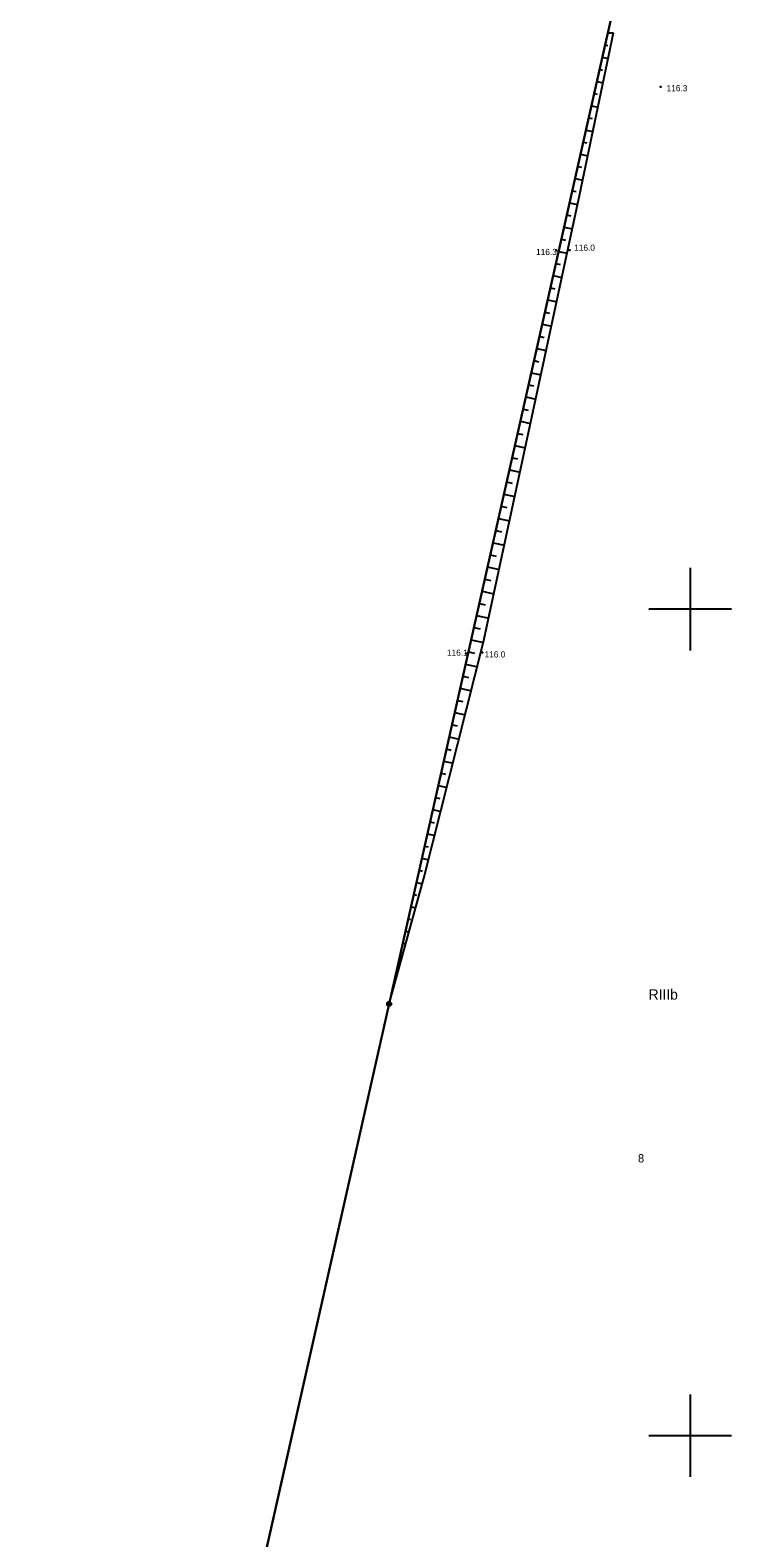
# Model space of a CAD drawing. Extents: x 6424617 to 6425697, y 5665845 to 5667190.
# Drawn here: x 6424820.1 to 6424906, y 5666387.6 to 5666570.1 of the extents above; entities that cross this region are included whole.
import ezdxf

# ---------------------------------------------------------------- set-up
doc = ezdxf.new("R2010")
doc.units = 0
for name, color, linetype in [('Warstwa 1', 7, 'Continuous'), ('Warstwa 10', 7, 'Continuous'), ('Warstwa 13', 7, 'Continuous'), ('Warstwa 15', 7, 'Continuous'), ('Warstwa 2', 7, 'Continuous'), ('Warstwa 20', 7, 'Continuous'), ('Warstwa 21', 7, 'Continuous'), ('Warstwa 6', 7, 'Continuous'), ('Warstwa 63', 7, 'Continuous')]:
    doc.layers.add(name, color=color, linetype=linetype)

msp = doc.modelspace()

# ---------------------------------------------------------------- linework, layer by layer
at = {"layer": 'Warstwa 1'}
for p, q in [((6424863.57, 5666452.24), (6424895.16, 5666592.47)), ((6424863.57, 5666452.24), (6424895.16, 5666592.47)), ((6424835.21, 5666326.25), (6424863.57, 5666452.24)), ((6424835.21, 5666326.25), (6424863.57, 5666452.24))]:
    msp.add_line(p, q, dxfattribs=at)
at = {"layer": 'Warstwa 10'}
for p, q in [((6424863.57, 5666452.24), (6424890.03, 5666569.72)), ((6424886.61, 5666550.03), (6424890.71, 5666569.71)), ((6424890.03, 5666569.72), (6424890.71, 5666569.71)), ((6424890.03, 5666569.72), (6424890.71, 5666569.71)), ((6424889.7, 5666568.25), (6424890.04, 5666568.21)), ((6424889.37, 5666566.78), (6424890.06, 5666566.63)), ((6424889.04, 5666565.32), (6424889.4, 5666565.23)), ((6424888.38, 5666562.38), (6424888.76, 5666562.29)), ((6424888.71, 5666563.85), (6424889.45, 5666563.68)), ((6424888.05, 5666560.91), (6424888.84, 5666560.73)), ((6424887.72, 5666559.44), (6424888.12, 5666559.35)), ((6424887.39, 5666557.97), (6424888.22, 5666557.78)), ((6424886.73, 5666555.04), (6424887.61, 5666554.83)), ((6424887.06, 5666556.5), (6424887.49, 5666556.41)), ((6424886.39, 5666553.57), (6424886.85, 5666553.46)), ((6424886.06, 5666552.1), (6424887, 5666551.89)), ((6424875, 5666496.03), (6424886.61, 5666550.03)), ((6424885.73, 5666550.63), (6424886.21, 5666550.52)), ((6424885.07, 5666547.69), (6424885.57, 5666547.58)), ((6424885.4, 5666549.16), (6424886.38, 5666548.94)), ((6424884.74, 5666546.23), (6424885.75, 5666546)), ((6424884.41, 5666544.76), (6424884.92, 5666544.64)), ((6424884.08, 5666543.29), (6424885.11, 5666543.05)), ((6424883.42, 5666540.35), (6424884.48, 5666540.11)), ((6424883.75, 5666541.82), (6424884.27, 5666541.7)), ((6424883.09, 5666538.88), (6424883.62, 5666538.76)), ((6424882.76, 5666537.41), (6424883.85, 5666537.17)), ((6424882.42, 5666535.95), (6424882.98, 5666535.82)), ((6424881.76, 5666533.01), (6424882.33, 5666532.88)), ((6424882.09, 5666534.48), (6424883.21, 5666534.22)), ((6424881.43, 5666531.54), (6424882.58, 5666531.28)), ((6424881.1, 5666530.07), (6424881.68, 5666529.94)), ((6424880.77, 5666528.6), (6424881.95, 5666528.34)), ((6424880.11, 5666525.67), (6424881.32, 5666525.39)), ((6424880.44, 5666527.13), (6424881.04, 5666527)), ((6424879.78, 5666524.2), (6424880.39, 5666524.06)), ((6424879.45, 5666522.73), (6424880.68, 5666522.45)), ((6424879.12, 5666521.26), (6424879.74, 5666521.12)), ((6424878.46, 5666518.32), (6424879.1, 5666518.18)), ((6424878.79, 5666519.79), (6424880.05, 5666519.5)), ((6424878.13, 5666516.85), (6424879.42, 5666516.57)), ((6424877.79, 5666515.39), (6424878.45, 5666515.24)), ((6424877.46, 5666513.92), (6424878.79, 5666513.62)), ((6424877.13, 5666512.45), (6424877.8, 5666512.3)), ((6424876.47, 5666509.51), (6424877.15, 5666509.36)), ((6424876.8, 5666510.98), (6424878.15, 5666510.67)), ((6424876.14, 5666508.04), (6424877.52, 5666507.73)), ((6424875.81, 5666506.58), (6424876.51, 5666506.42)), ((6424875.48, 5666505.11), (6424876.89, 5666504.78)), ((6424874.82, 5666502.17), (6424876.25, 5666501.84)), ((6424875.15, 5666503.64), (6424875.86, 5666503.48)), ((6424874.49, 5666500.7), (6424875.21, 5666500.54)), ((6424874.16, 5666499.23), (6424875.62, 5666498.9)), ((6424873.83, 5666497.76), (6424874.57, 5666497.6)), ((6424867.79, 5666467.44), (6424875, 5666496.03)), ((6424873.16, 5666494.83), (6424873.89, 5666494.66)), ((6424873.5, 5666496.3), (6424874.99, 5666495.96)), ((6424872.83, 5666493.36), (6424874.25, 5666493.04)), ((6424872.5, 5666491.89), (6424873.19, 5666491.74)), ((6424872.17, 5666490.42), (6424873.51, 5666490.12)), ((6424871.51, 5666487.49), (6424872.78, 5666487.2)), ((6424871.84, 5666488.95), (6424872.49, 5666488.81)), ((6424871.18, 5666486.02), (6424871.79, 5666485.88)), ((6424870.85, 5666484.55), (6424872.04, 5666484.28)), ((6424870.52, 5666483.08), (6424871.09, 5666482.95)), ((6424869.86, 5666480.14), (6424870.39, 5666480.02)), ((6424870.19, 5666481.61), (6424871.3, 5666481.36)), ((6424869.53, 5666478.67), (6424870.56, 5666478.44)), ((6424869.2, 5666477.21), (6424869.7, 5666477.09)), ((6424868.86, 5666475.74), (6424869.83, 5666475.52)), ((6424868.2, 5666472.8), (6424869.09, 5666472.6)), ((6424868.53, 5666474.27), (6424869, 5666474.16)), ((6424867.87, 5666471.33), (6424868.3, 5666471.24)), ((6424867.54, 5666469.86), (6424868.35, 5666469.68)), ((6424863.57, 5666452.24), (6424867.79, 5666467.44)), ((6424867.21, 5666468.4), (6424867.59, 5666468.31)), ((6424866.55, 5666465.46), (6424866.87, 5666465.38)), ((6424866.88, 5666466.93), (6424867.6, 5666466.76)), ((6424866.22, 5666463.99), (6424866.79, 5666463.86)), ((6424865.89, 5666462.52), (6424866.14, 5666462.46)), ((6424865.56, 5666461.05), (6424865.99, 5666460.96)), ((6424864.9, 5666458.12), (6424865.18, 5666458.05)), ((6424865.23, 5666459.58), (6424865.41, 5666459.54)), ((6424864.57, 5666456.65), (6424864.67, 5666456.62)), ((6424864.23, 5666455.18), (6424864.38, 5666455.15))]:
    msp.add_line(p, q, dxfattribs=at)
msp.add_circle((6424863.57, 5666452.24), 0.25, dxfattribs=at)
at = {"layer": 'Warstwa 13'}
for centre in [(6424896.43, 5666563.19), (6424883.8, 5666543.41), (6424885.4, 5666543.44), (6424872.88, 5666494.63), (6424874.84, 5666494.76)]:
    msp.add_circle(centre, 0.045, dxfattribs=at)
at = {"layer": 'Warstwa 20'}
msp.add_line((6424863.57, 5666452.24), (6424890.03, 5666569.72), dxfattribs=at)
at = {"layer": 'Warstwa 21'}
for p, q in [((6424886.61, 5666550.03), (6424890.71, 5666569.71)), ((6424875, 5666496.03), (6424886.61, 5666550.03)), ((6424867.79, 5666467.44), (6424875, 5666496.03)), ((6424863.57, 5666452.24), (6424867.79, 5666467.44))]:
    msp.add_line(p, q, dxfattribs=at)
at = {"layer": 'Warstwa 6'}
msp.add_lwpolyline([(6424716.45, 5666344.63), (6424730.04, 5666344.35), (6424778.08, 5666337.65), (6424835.21, 5666326.25), (6424863.57, 5666452.24), (6424895.16, 5666592.47), (6424930.46, 5666744.03), (6424963.64, 5666736.21), (6424996.49, 5666728.81), (6425001.61, 5666749.86), (6425004.59, 5666768.33), (6425004.27, 5666802.33), (6425009.8, 5666830.19), (6425016.63, 5666870.23), (6425020.01, 5666882.89), (6425015.31, 5666889.08), (6425007.51, 5666895.23), (6424957.01, 5666906.7), (6424920.8, 5666746.62), (6424867.64, 5666760.89), (6424902.78, 5666916.32), (6424874.44, 5666914.51), (6424858.5, 5666915.71), (6424844.87, 5666917.42)], dxfattribs=at)
msp.add_lwpolyline([(6424835.21, 5666326.25), (6424854.22, 5666322.77), (6424872.34, 5666313.51), (6424890.18, 5666301.67), (6424901.94, 5666342.13), (6424903.49, 5666349.42), (6424940.64, 5666499.33), (6424960.37, 5666579.88), (6424928.89, 5666586.01), (6424895.16, 5666592.47), (6424863.57, 5666452.24)], close=True, dxfattribs=at)
at = {"layer": 'Warstwa 63'}
for p, q in [((6424900, 5666505), (6424900, 5666495)), ((6424905, 5666500), (6424895, 5666500)), ((6424900, 5666405), (6424900, 5666395)), ((6424905, 5666400), (6424895, 5666400))]:
    msp.add_line(p, q, dxfattribs=at)

# ---------------------------------------------------------------- texts
at = {"layer": 'Warstwa 13'}
for s, p in [('116.3', (6424897.15, 5666562.66)), ('116.0', (6424885.96, 5666543.36)), ('116.3', (6424881.35, 5666542.84)), ('116.1', (6424870.57, 5666494.36)), ('116.0', (6424875.12, 5666494.15))]:
    msp.add_text(s, height=0.75, dxfattribs=at).set_placement(p)
at = {"layer": 'Warstwa 15'}
msp.add_text('8', height=1, dxfattribs=at).set_placement((6424893.68, 5666433.06))
at = {"layer": 'Warstwa 2'}
msp.add_text('RIIIb', height=1.25, dxfattribs=at).set_placement((6424894.97, 5666452.75))

doc.saveas('drawing.dxf')
